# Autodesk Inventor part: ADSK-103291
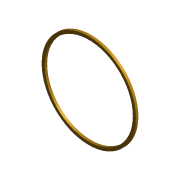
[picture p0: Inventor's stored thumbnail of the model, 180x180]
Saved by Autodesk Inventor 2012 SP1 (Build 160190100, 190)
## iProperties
Shininess: 0.0
Created: 2000-04
Part Number: ADSK-103291
Document SubType Name: Modeling
Stock Number: ADSK-103291
Density: 1 g/cm^3
Material: Default
Density: 0.0
Volumn: 0.0
Area: 0.0
PropertySet Name: Model Information
Control State: 0
Checked Out: False
Master: False
Author: gao
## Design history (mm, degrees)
node "Extrusion1" dims "d2" = 4, "d3" = 0
  sketch "Sketch1"
    geometry: C1 r 72.5 at (0, 0); C2 r 77.5 at (0, 0)
    constraints: 2 centre point, 1 coincident
    dimensions: "d0" = 145 diameter of C1; "d1" = 155 diameter of C2
body "Solid1"
